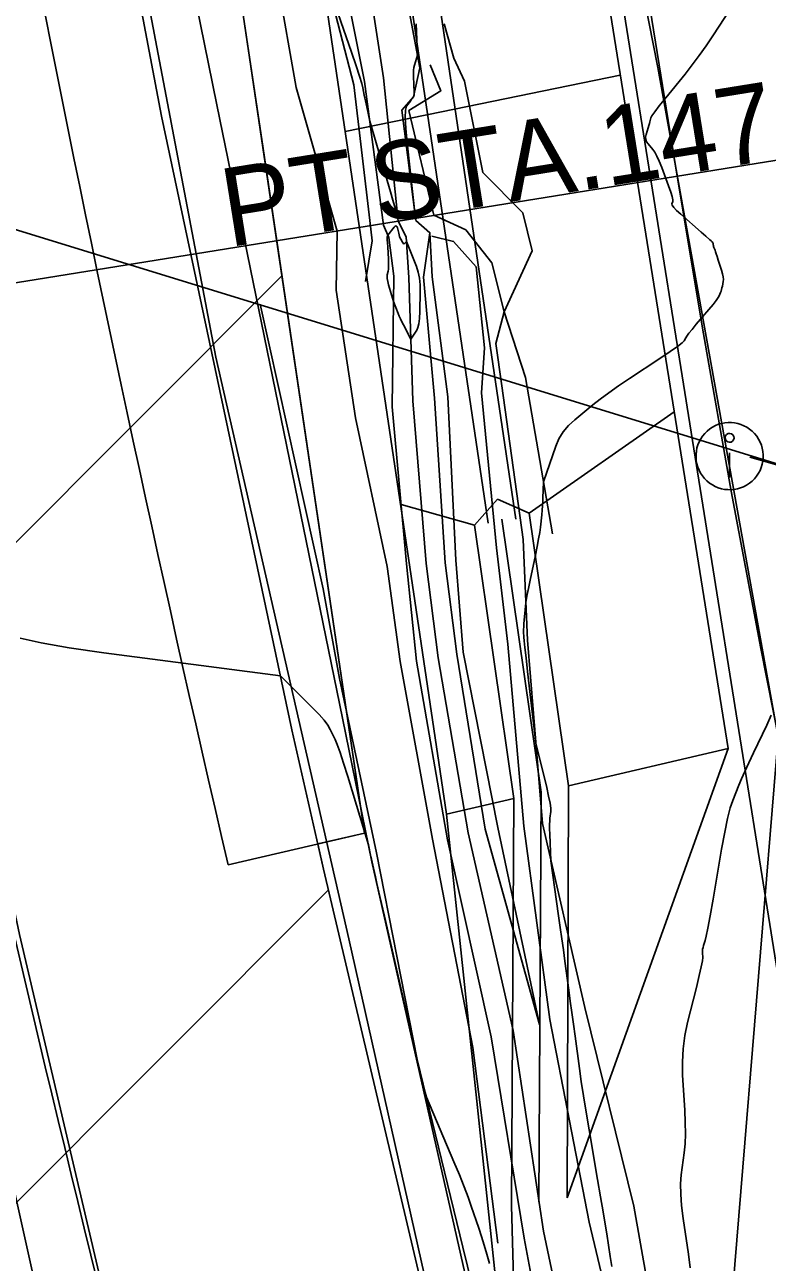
# Model space of a CAD drawing. Extents: x 2030588 to 2035216, y 462285 to 465007.
# Drawn here: x 2031270.79 to 2031297.29, y 464196.54 to 464240.7 of the extents above; entities that cross this region are included whole.
import ezdxf

# ---------------------------------------------------------------- set-up
doc = ezdxf.new("R2010")
doc.units = 0
for name, color, linetype in [('DR_P_Ditch', 7, 'Continuous'), ('DR_P_Drive_Pipe', 7, 'Continuous'), ('DR_X_Ditch', 7, 'Continuous'), ('DT_P_Pavement_Surface', 7, 'Continuous'), ('DT_P_Slope_Break_Line', 7, 'Continuous'), ('DT_X_Contour_Major', 7, 'Continuous'), ('DT_X_Contour_Minor', 7, 'Continuous'), ('DV_X_Property_Line', 7, 'Continuous'), ('GE_X_Alignment', 7, 'Continuous'), ('MD_P_CONST_LIMITS', 7, 'Continuous'), ('MT_P_Temp_Road', 7, 'Continuous'), ('PV_X_COP', 7, 'Continuous'), ('PV_X_EOP', 7, 'Continuous'), ('PV_X_Shoulder_Aggregate', 7, 'Continuous'), ('RD_X_Fence', 7, 'Continuous'), ('RW_X_CL', 7, 'Continuous'), ('RW_X_CL_100_Cardinal_Points', 7, 'Continuous'), ('RW_X_Esmt_SH', 7, 'Continuous'), ('SV_X_Break_Lines', 7, 'Continuous'), ('SV_X_Mon_Cells_Found', 7, 'Continuous'), ('SV_X_Toe_of_Slope', 7, 'Continuous'), ('SV_X_Top_of_Bank', 7, 'Continuous'), ('UT_X_Electric', 7, 'Continuous'), ('UT_X_Telecom', 7, 'Continuous')]:
    doc.layers.add(name, color=color, linetype=linetype)

msp = doc.modelspace()

# ---------------------------------------------------------------- linework, layer by layer
at = {"layer": 'DR_P_Ditch'}
msp.add_lwpolyline([(2031289.138, 464198.702), (2031289.214, 464213.319), (2031287.809, 464223.054)], dxfattribs=at)
at = {"layer": 'DR_P_Drive_Pipe'}
for p, q in [((2031285.387, 464242.84), (2031288.317, 464223.058)), ((2031284.398, 464242.694), (2031287.328, 464222.912))]:
    msp.add_line(p, q, dxfattribs=at)
at = {"layer": 'DR_X_Ditch'}
msp.add_lwpolyline([(2031296.503, 464165.775), (2031294.416, 464172.894), (2031292.48, 464180.474), (2031291.756, 464186.133), (2031290.713, 464190.937), (2031289.295, 464197.655), (2031288.219, 464204.814), (2031286.616, 464211.861), (2031285.537, 464218.105), (2031285.112, 464221.471), (2031284.631, 464227.278), (2031284.497, 464231.677), (2031284.399, 464233.135), (2031284.113, 464233.687), (2031283.585, 464238.805), (2031282.994, 464242.68)], dxfattribs=at)
at = {"layer": 'DT_P_Pavement_Surface'}
for p, q in [((2031261.179, 464212.949), (2031279.966, 464231.735)), ((2031264.485, 464192.687), (2031281.619, 464209.821))]:
    msp.add_line(p, q, dxfattribs=at)
msp.add_lwpolyline([(2031278.406, 464242.26), (2031279.291, 464236.286), (2031282.911, 464211.855), (2031281.24, 464211.467), (2031281.443, 464210.564), (2031286.324, 464189.894), (2031290.945, 464171.988), (2031296.143, 464154.308), (2031300.701, 464140.215), (2031308.554, 464119.142), (2031298.227, 464114.968), (2031289.065, 464111.177), (2031284.681, 464122.798), (2031281.552, 464131.387), (2031280.87, 464133.486), (2031276.172, 464147.96), (2031272.883, 464159.049), (2031266.889, 464182.219), (2031261.238, 464206.822), (2031262.457, 464207.105), (2031257.072, 464231.726), (2031252.323, 464256.477)], dxfattribs=at)
at = {"layer": 'DT_P_Slope_Break_Line'}
for p, q in [((2031280.277, 464250.041), (2031285.833, 464212.534)), ((2031291.424, 464242.739), (2031295.894, 464214.87)), ((2031292.04, 464238.902), (2031285.659, 464237.593)), ((2031282.225, 464236.888), (2031285.659, 464237.593)), ((2031288.786, 464223.271), (2031293.967, 464226.886)), ((2031286.833, 464222.838), (2031287.652, 464223.768)), ((2031287.652, 464223.768), (2031288.786, 464223.271)), ((2031286.833, 464222.838), (2031284.222, 464223.576)), ((2031288.786, 464223.271), (2031290.188, 464213.545)), ((2031288.24, 464213.093), (2031286.833, 464222.838)), ((2031295.894, 464214.87), (2031290.142, 464198.846)), ((2031295.894, 464214.87), (2031290.188, 464213.545)), ((2031290.188, 464213.545), (2031290.142, 464198.846)), ((2031285.833, 464212.534), (2031288.24, 464213.093)), ((2031288.162, 464198.563), (2031288.24, 464213.093)), ((2031285.833, 464212.534), (2031288.455, 464187.817)), ((2031288.455, 464187.817), (2031288.162, 464198.563))]:
    msp.add_line(p, q, dxfattribs=at)
at = {"layer": 'DT_X_Contour_Major'}
msp.add_lwpolyline([(2031297.429, 464216.069), (2031297.265, 464215.712), (2031296.79, 464214.717), (2031296.625, 464214.365), (2031296.483, 464214.055), (2031296.365, 464213.788), (2031296.271, 464213.563), (2031296.052, 464213.018), (2031295.966, 464212.756), (2031295.872, 464212.379), (2031295.769, 464211.886), (2031295.658, 464211.277), (2031295.35, 464209.5), (2031295.246, 464208.909), (2031295.165, 464208.466), (2031295.108, 464208.173), (2031295.074, 464208.029), (2031295.013, 464207.844), (2031294.993, 464207.775), (2031294.98, 464207.709), (2031294.974, 464207.644), (2031294.974, 464207.581), (2031294.983, 464207.415), (2031294.971, 464207.301), (2031294.93, 464207.086), (2031294.858, 464206.769), (2031294.756, 464206.35), (2031294.444, 464205.098), (2031294.345, 464204.628), (2031294.282, 464204.159), (2031294.256, 464203.69), (2031294.266, 464203.222), (2031294.341, 464201.974), (2031294.361, 464201.528), (2031294.364, 464201.124), (2031294.35, 464200.764), (2031294.32, 464200.446), (2031294.218, 464199.657), (2031294.193, 464199.339), (2031294.196, 464198.974), (2031294.226, 464198.563), (2031294.282, 464198.107), (2031294.471, 464196.829), (2031294.536, 464196.343)], dxfattribs=at)
at = {"layer": 'DT_X_Contour_Minor'}
for points in [[(2031284.75, 464240.728), (2031284.802, 464239.609), (2031284.695, 464239.253), (2031284.676, 464239.171), (2031284.664, 464239.077), (2031284.659, 464238.971), (2031284.661, 464238.854), (2031284.689, 464238.278), (2031284.678, 464238.182), (2031284.676, 464238.164), (2031284.674, 464238.149), (2031284.671, 464238.14), (2031284.668, 464238.134), (2031284.659, 464238.125), (2031284.649, 464238.113), (2031284.628, 464238.084), (2031284.594, 464238.039), (2031284.547, 464237.977), (2031284.408, 464237.789), (2031284.37, 464237.655), (2031284.361, 464237.393), (2031284.382, 464237.003), (2031284.431, 464236.486), (2031284.731, 464233.774), (2031284.307, 464233.949), (2031284.226, 464233.979), (2031284.168, 464233.995), (2031284.131, 464233.996), (2031284.115, 464233.983), (2031284.093, 464233.887), (2031284.014, 464234.134), (2031283.983, 464234.237), (2031283.923, 464234.44), (2031283.835, 464234.743), (2031283.717, 464235.147), (2031283.103, 464237.263), (2031282.99, 464237.77), (2031282.966, 464237.877), (2031282.944, 464237.982), (2031282.924, 464238.085), (2031282.905, 464238.185), (2031282.856, 464238.45), (2031282.816, 464238.603), (2031282.735, 464238.866), (2031282.612, 464239.239), (2031282.448, 464239.721), (2031281.581, 464242.225)], [(2031295.969, 464241.264), (2031295.34, 464240.3), (2031295.102, 464239.944), (2031294.858, 464239.599), (2031294.607, 464239.264), (2031294.351, 464238.941), (2031293.661, 464238.093), (2031293.433, 464237.809), (2031293.269, 464237.596), (2031293.167, 464237.453), (2031293.127, 464237.38), (2031293.107, 464237.277), (2031293.096, 464237.232), (2031293.081, 464237.174), (2031293.06, 464237.104), (2031293.035, 464237.021), (2031292.96, 464236.781), (2031292.943, 464236.693), (2031292.95, 464236.608), (2031292.98, 464236.527), (2031293.034, 464236.449), (2031293.207, 464236.246), (2031293.275, 464236.149), (2031293.35, 464236.009), (2031293.431, 464235.828), (2031293.519, 464235.604), (2031293.761, 464234.949), (2031293.839, 464234.731), (2031293.891, 464234.565), (2031293.917, 464234.453), (2031293.917, 464234.393), (2031293.882, 464234.305), (2031293.892, 464234.258), (2031293.947, 464234.181), (2031294.049, 464234.076), (2031294.196, 464233.942), (2031294.931, 464233.299), (2031295.097, 464233.154), (2031295.241, 464233.029), (2031295.288, 464232.986), (2031295.322, 464232.95), (2031295.343, 464232.923), (2031295.35, 464232.904), (2031295.353, 464232.863), (2031295.356, 464232.845), (2031295.361, 464232.821), (2031295.371, 464232.791), (2031295.383, 464232.756), (2031295.421, 464232.653), (2031295.439, 464232.602), (2031295.464, 464232.526), (2031295.497, 464232.427), (2031295.537, 464232.302), (2031295.654, 464231.938), (2031295.691, 464231.811), (2031295.713, 464231.702), (2031295.722, 464231.611), (2031295.716, 464231.538), (2031295.683, 464231.368), (2031295.669, 464231.306), (2031295.655, 464231.249), (2031295.639, 464231.197), (2031295.621, 464231.149), (2031295.573, 464231.028), (2031295.537, 464230.964), (2031295.462, 464230.861), (2031295.35, 464230.72), (2031295.201, 464230.54), (2031294.753, 464230.01), (2031294.603, 464229.83), (2031294.49, 464229.691), (2031294.413, 464229.591), (2031294.374, 464229.53), (2031294.316, 464229.421), (2031294.247, 464229.352), (2031294.08, 464229.224), (2031293.816, 464229.039), (2031293.456, 464228.796), (2031292.365, 464228.072), (2031291.977, 464227.81), (2031291.63, 464227.566), (2031291.325, 464227.341), (2031291.061, 464227.134), (2031290.412, 464226.607), (2031290.187, 464226.4), (2031290, 464226.174), (2031289.85, 464225.929), (2031289.738, 464225.665), (2031289.3, 464224.391), (2031289.28, 464223.802), (2031289.274, 464223.67), (2031289.264, 464223.529), (2031289.252, 464223.378), (2031289.236, 464223.217), (2031289.189, 464222.775), (2031289.164, 464222.587), (2031289.127, 464222.358), (2031289.076, 464222.086), (2031289.012, 464221.773), (2031288.822, 464220.879), (2031288.76, 464220.584), (2031288.715, 464220.367), (2031288.688, 464220.229), (2031288.678, 464220.17), (2031288.673, 464220.077), (2031288.611, 464219.448), (2031288.6, 464219.321), (2031288.593, 464219.21), (2031288.59, 464219.116), (2031288.591, 464219.038), (2031288.601, 464218.851), (2031288.612, 464218.722), (2031288.638, 464218.473), (2031288.679, 464218.105), (2031288.734, 464217.618), (2031289.027, 464215.069), (2031289.413, 464213.479), (2031289.484, 464213.17), (2031289.532, 464212.925), (2031289.556, 464212.743), (2031289.557, 464212.625), (2031289.528, 464212.394), (2031289.52, 464212.293), (2031289.517, 464212.163), (2031289.518, 464212.003), (2031289.525, 464211.814), (2031289.567, 464210.865), (2031289.839, 464208.908), (2031289.896, 464208.493), (2031289.953, 464208.085), (2031290.008, 464207.685), (2031290.062, 464207.292), (2031290.203, 464206.254), (2031290.257, 464205.86), (2031290.312, 464205.455), (2031290.369, 464205.039), (2031290.426, 464204.612), (2031290.582, 464203.459), (2031290.648, 464202.997), (2031290.727, 464202.478), (2031290.82, 464201.9), (2031290.927, 464201.265), (2031291.231, 464199.492), (2031291.337, 464198.873), (2031291.427, 464198.343), (2031291.499, 464197.904), (2031291.556, 464197.555), (2031291.684, 464196.744), (2031291.743, 464196.392)], [(2031284.41, 464232.97), (2031284.762, 464232.077), (2031284.828, 464231.876), (2031284.872, 464231.657), (2031284.896, 464231.421), (2031284.9, 464231.166), (2031284.881, 464230.463), (2031284.869, 464230.223), (2031284.848, 464230.033), (2031284.816, 464229.892), (2031284.776, 464229.799), (2031284.564, 464229.482), (2031284.3, 464229.992), (2031284.246, 464230.099), (2031284.197, 464230.201), (2031284.153, 464230.299), (2031284.115, 464230.393), (2031283.946, 464230.819), (2031283.771, 464231.422), (2031283.74, 464231.541), (2031283.721, 464231.64), (2031283.715, 464231.719), (2031283.722, 464231.779), (2031283.758, 464231.911), (2031283.768, 464231.974), (2031283.773, 464232.066), (2031283.771, 464232.187), (2031283.764, 464232.335), (2031283.738, 464232.769), (2031283.729, 464232.913), (2031283.725, 464233.02), (2031283.723, 464233.091), (2031283.725, 464233.124), (2031283.742, 464233.194), (2031283.964, 464233.473), (2031284.007, 464233.516), (2031284.043, 464233.527), (2031284.07, 464233.506), (2031284.09, 464233.452), (2031284.132, 464233.265), (2031284.148, 464233.198), (2031284.166, 464233.139), (2031284.186, 464233.088), (2031284.208, 464233.044), (2031284.267, 464232.938), (2031284.289, 464232.906), (2031284.308, 464232.887), (2031284.326, 464232.883), (2031284.341, 464232.892), (2031284.41, 464232.97)], [(2031287.377, 464196.503), (2031287.283, 464196.832), (2031287.187, 464197.15), (2031287.09, 464197.46), (2031286.99, 464197.76), (2031286.723, 464198.548), (2031286.609, 464198.869), (2031286.467, 464199.239), (2031286.298, 464199.659), (2031286.101, 464200.129), (2031285.118, 464202.439), (2031285.009, 464202.848), (2031284.958, 464203.057), (2031284.853, 464203.508), (2031284.693, 464204.2), (2031284.479, 464205.135), (2031283.834, 464207.949), (2031283.619, 464208.887), (2031283.459, 464209.591), (2031283.352, 464210.059), (2031283.299, 464210.292), (2031283.23, 464210.602), (2031283.205, 464210.715), (2031283.182, 464210.821), (2031283.16, 464210.92), (2031283.14, 464211.013), (2031283.051, 464211.432), (2031282.311, 464213.878), (2031282.164, 464214.354), (2031282.041, 464214.732), (2031281.94, 464215.013), (2031281.863, 464215.197), (2031281.689, 464215.558), (2031281.601, 464215.707), (2031281.467, 464215.884), (2031281.289, 464216.088), (2031281.065, 464216.319), (2031279.914, 464217.463), (2031273.605, 464218.293), (2031272.372, 464218.47), (2031271.376, 464218.643), (2031270.618, 464218.814)]]:
    msp.add_lwpolyline(points, dxfattribs=at)
at = {"layer": 'DV_X_Property_Line'}
msp.add_line((2031636.207, 464120.963), (2031264.413, 464235.242), dxfattribs=at)
at = {"layer": 'GE_X_Alignment'}
msp.add_ellipse((2032214.825, 464428.293), major_axis=(-647.882, 721.538), ratio=0.999987, start_param=0.998641, end_param=1.129131, dxfattribs=at)
at = {"layer": 'MD_P_CONST_LIMITS'}
msp.add_lwpolyline([(2031304.871, 464099.462), (2031318.532, 464105.655), (2031311.904, 464118.546), (2031304.38, 464141.463), (2031297.225, 464164.67), (2031295.574, 464189.665), (2031297.675, 464215.284), (2031293.386, 464239.179), (2031288.691, 464262.969), (2031290.634, 464288.11), (2031294.17, 464303.872), (2031299.488, 464314.858)], dxfattribs=at)
at = {"layer": 'MT_P_Temp_Road'}
for p, q in [((2031282.911, 464211.855), (2031278.406, 464242.26)), ((2031278.041, 464210.724), (2031282.911, 464211.855))]:
    msp.add_line(p, q, dxfattribs=at)
msp.add_ellipse((2032214.825, 464428.293), major_axis=(-641.893, 716.165), ratio=0.999987, start_param=0.999542, end_param=1.068244, dxfattribs=at)
at = {"layer": 'PV_X_COP'}
msp.add_lwpolyline([(2031345.188, 464029.832), (2031333.67, 464047.134), (2031321.647, 464066.894), (2031312.766, 464083.536), (2031304.429, 464100.871), (2031297.296, 464118.161), (2031290.962, 464134.785), (2031285.598, 464151.007), (2031280.258, 464168.89), (2031275.568, 464187.058), (2031270.599, 464208.238), (2031269.533, 464213.253), (2031265.078, 464235.308), (2031261.071, 464256.548), (2031257.559, 464275.914), (2031253.749, 464297.335), (2031250.237, 464316.556), (2031248.155, 464328.465)], dxfattribs=at)
at = {"layer": 'PV_X_EOP'}
msp.add_lwpolyline([(2031353.162, 464035.71), (2031341.874, 464052.676), (2031332.716, 464067.744), (2031330.521, 464071.931), (2031322.023, 464088.196), (2031314.108, 464105.099), (2031307.351, 464122.147), (2031301.267, 464138.466), (2031296.143, 464154.308), (2031290.945, 464171.988), (2031286.324, 464189.894), (2031281.443, 464210.564), (2031280.322, 464215.544), (2031275.666, 464237.435), (2031271.643, 464258.648), (2031268.07, 464277.87), (2031264.482, 464299.113), (2031261, 464318.439), (2031259.92, 464324.373)], dxfattribs=at)
at = {"layer": 'PV_X_Shoulder_Aggregate'}
msp.add_lwpolyline([(2031322.799, 464088.616), (2031315.02, 464105.504), (2031308.326, 464122.489), (2031302.318, 464138.797), (2031297.302, 464154.717), (2031292.39, 464172.399), (2031287.828, 464190.274), (2031283.175, 464210.826), (2031282.124, 464215.96), (2031277.635, 464237.84), (2031273.355, 464258.914)], dxfattribs=at)
at = {"layer": 'RD_X_Fence'}
msp.add_lwpolyline([(2031296.661, 464225.271), (2031315.862, 464219.785), (2031324.624, 464216.973), (2031330.829, 464230.155), (2031335.011, 464242.221), (2031347.019, 464246.547), (2031359.451, 464251.293)], dxfattribs=at)
at = {"layer": 'RW_X_CL'}
msp.add_ellipse((2031830.081, 464321.523), major_axis=(-382.715, 426.319), ratio=0.999987, start_param=0.998751, end_param=1.776295, dxfattribs=at)
at = {"layer": 'RW_X_CL_100_Cardinal_Points'}
msp.add_line((2031264.454, 464230.531), (2031308.878, 464237.678), dxfattribs=at)
at = {"layer": 'RW_X_Esmt_SH'}
msp.add_line((2031294.07, 464235.295), (2031222.33, 464681.217), dxfattribs=at)
msp.add_lwpolyline([(2031309.17, 464168.574), (2031307.591, 464174.056), (2031306.071, 464179.554), (2031304.608, 464185.068), (2031303.203, 464190.596), (2031301.856, 464196.14), (2031300.568, 464201.697), (2031299.338, 464207.267), (2031298.167, 464212.85), (2031297.054, 464218.445), (2031296.001, 464224.051), (2031295.006, 464229.668), (2031294.07, 464235.295)], dxfattribs=at)
at = {"layer": 'SV_X_Break_Lines'}
for points in [[(2031282.947, 464231.538), (2031283.186, 464232.985), (2031283.1, 464233.71), (2031282.533, 464238.56), (2031281.555, 464242.327), (2031281.352, 464244.842), (2031281.407, 464245.871), (2031280.309, 464249.266), (2031278.451, 464255.467), (2031277.014, 464259.841), (2031275.774, 464265.918), (2031275.32, 464269.267), (2031273.515, 464278.626), (2031272.571, 464284.096), (2031271.385, 464291.028), (2031269.801, 464300.113), (2031269.085, 464305.912), (2031268.352, 464306.933), (2031267.595, 464308.094), (2031265.679, 464310.232)], [(2031289.621, 464222.53), (2031288.658, 464228.117), (2031287.896, 464230.453), (2031288.897, 464232.629), (2031288.558, 464233.988), (2031287.131, 464235.433), (2031286.475, 464238.685), (2031286.097, 464239.508), (2031285.759, 464240.73)], [(2031279.184, 464230.728), (2031281.431, 464220.57), (2031282.015, 464217.367), (2031283.335, 464211.146), (2031284.794, 464203.774), (2031286.418, 464197.084), (2031288.119, 464190.155), (2031289.378, 464185.603), (2031290.824, 464180.11), (2031293.444, 464172.527), (2031295.235, 464165.396), (2031296.873, 464159.344), (2031297.803, 464155.004), (2031300.31, 464146.294), (2031302.745, 464138.963), (2031304.623, 464134.105), (2031306.989, 464127.43), (2031308.732, 464122.376), (2031310.328, 464118.347), (2031313.222, 464111.465), (2031315.576, 464105.532), (2031318.909, 464097.312)]]:
    msp.add_lwpolyline(points, dxfattribs=at)
at = {"layer": 'SV_X_Mon_Cells_Found'}
msp.add_line((2031295.941, 464225.424), (2031295.941, 464224.541), dxfattribs=at)
for centre, major_axis in [((2031295.941, 464225.308), (0.801, -0.893)), ((2031295.941, 464225.959), (0.107, -0.119))]:
    msp.add_ellipse(centre, major_axis=major_axis, ratio=0.999987, dxfattribs=at)
at = {"layer": 'SV_X_Toe_of_Slope'}
for points in [[(2031293.774, 464172.608), (2031291.435, 464180.285), (2031290.729, 464185.879), (2031289.893, 464190.553), (2031288.611, 464197.405), (2031287.426, 464204.588), (2031285.872, 464211.617), (2031284.765, 464217.99), (2031284.409, 464221.464), (2031283.902, 464227.062), (2031283.957, 464231.729), (2031283.779, 464233.107), (2031283.593, 464233.552), (2031282.916, 464238.677), (2031282.163, 464242.433)], [(2031289.151, 464205.027), (2031287.218, 464211.992), (2031286.208, 464218.238), (2031285.796, 464221.496), (2031285.411, 464227.374), (2031285.021, 464231.698), (2031285.246, 464233.279), (2031284.738, 464233.72), (2031284.244, 464237.651), (2031284.656, 464238.13), (2031284.884, 464239.166), (2031284.485, 464241.32)], [(2031285.316, 464233.158), (2031286.09, 464232.97), (2031286.896, 464232.063), (2031287.199, 464229.173), (2031287.082, 464227.563), (2031287.628, 464222.04), (2031288.032, 464218.598), (2031288.594, 464212.108), (2031289.523, 464205.203), (2031290.93, 464197.975), (2031292.472, 464191.495), (2031292.994, 464186.424), (2031293.827, 464180.942), (2031295.205, 464173.02), (2031297.242, 464165.988)]]:
    msp.add_lwpolyline(points, dxfattribs=at)
at = {"layer": 'SV_X_Top_of_Bank'}
for points in [[(2031279.815, 464242.178), (2031280.478, 464238.457), (2031281.931, 464233.336), (2031281.898, 464231.227), (2031282.584, 464226.67), (2031283.721, 464221.368), (2031284.185, 464217.979), (2031285.334, 464211.635), (2031286.778, 464204.206), (2031287.667, 464197.221)], [(2031285.389, 464233.908), (2031284.496, 464237.638), (2031285.633, 464238.341), (2031285.25, 464239.264)], [(2031285.389, 464233.908), (2031286.523, 464233.387), (2031287.459, 464232.202), (2031287.896, 464230.453), (2031287.594, 464229.321), (2031287.807, 464227.816), (2031288.573, 464222.336), (2031288.732, 464218.735), (2031289.258, 464212.201), (2031290.775, 464205.638), (2031292.525, 464198.542), (2031293.682, 464192.026), (2031294.638, 464186.768), (2031296.052, 464181.312), (2031298.162, 464173.534), (2031299.494, 464166.843)], [(2031285.246, 464233.279), (2031285.332, 464231.708), (2031285.887, 464227.421), (2031286.174, 464221.59), (2031286.438, 464218.309), (2031287.675, 464212.054), (2031289.151, 464205.027)]]:
    msp.add_lwpolyline(points, dxfattribs=at)
at = {"layer": 'UT_X_Electric'}
msp.add_lwpolyline([(2031221.843, 464713.466), (2031231.941, 464645.283), (2031244.284, 464562.24), (2031252.852, 464504.34), (2031260, 464456.218), (2031264.868, 464423.288), (2031269.313, 464393.306), (2031274.036, 464361.48), (2031280.969, 464314.78), (2031288.221, 464265.917), (2031292.226, 464240.822), (2031300.292, 464190.304), (2031337.855, 463955.944)], dxfattribs=at)
at = {"layer": 'UT_X_Telecom'}
msp.add_lwpolyline([(2031361.709, 464028.542), (2031356.786, 464035.327), (2031347.681, 464048.933), (2031339.944, 464060.397), (2031329.726, 464073.814), (2031321.673, 464087.15), (2031313.33, 464106.65), (2031305.91, 464124.388), (2031298.718, 464143.455), (2031292.601, 464165.642), (2031287.039, 464187.229), (2031282.348, 464208.081), (2031277.602, 464228.834), (2031275.079, 464242.094), (2031273.133, 464253.288), (2031272.708, 464257.728), (2031274.398, 464259.6), (2031278.694, 464259.868), (2031283.757, 464259.769), (2031285.497, 464261.094)], dxfattribs=at)

# ---------------------------------------------------------------- texts
at = {"layer": 'RW_X_CL_100_Cardinal_Points'}
for s, p in [('147+48.30', (2031291.559, 464234.929)), (' STA. ', (2031282.355, 464233.448)), ('PT', (2031278.06, 464232.757))]:
    msp.add_text(s, height=2.7997, rotation=9.1388, dxfattribs=at).set_placement(p)

doc.saveas('drawing.dxf')
